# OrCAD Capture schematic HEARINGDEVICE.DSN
size A
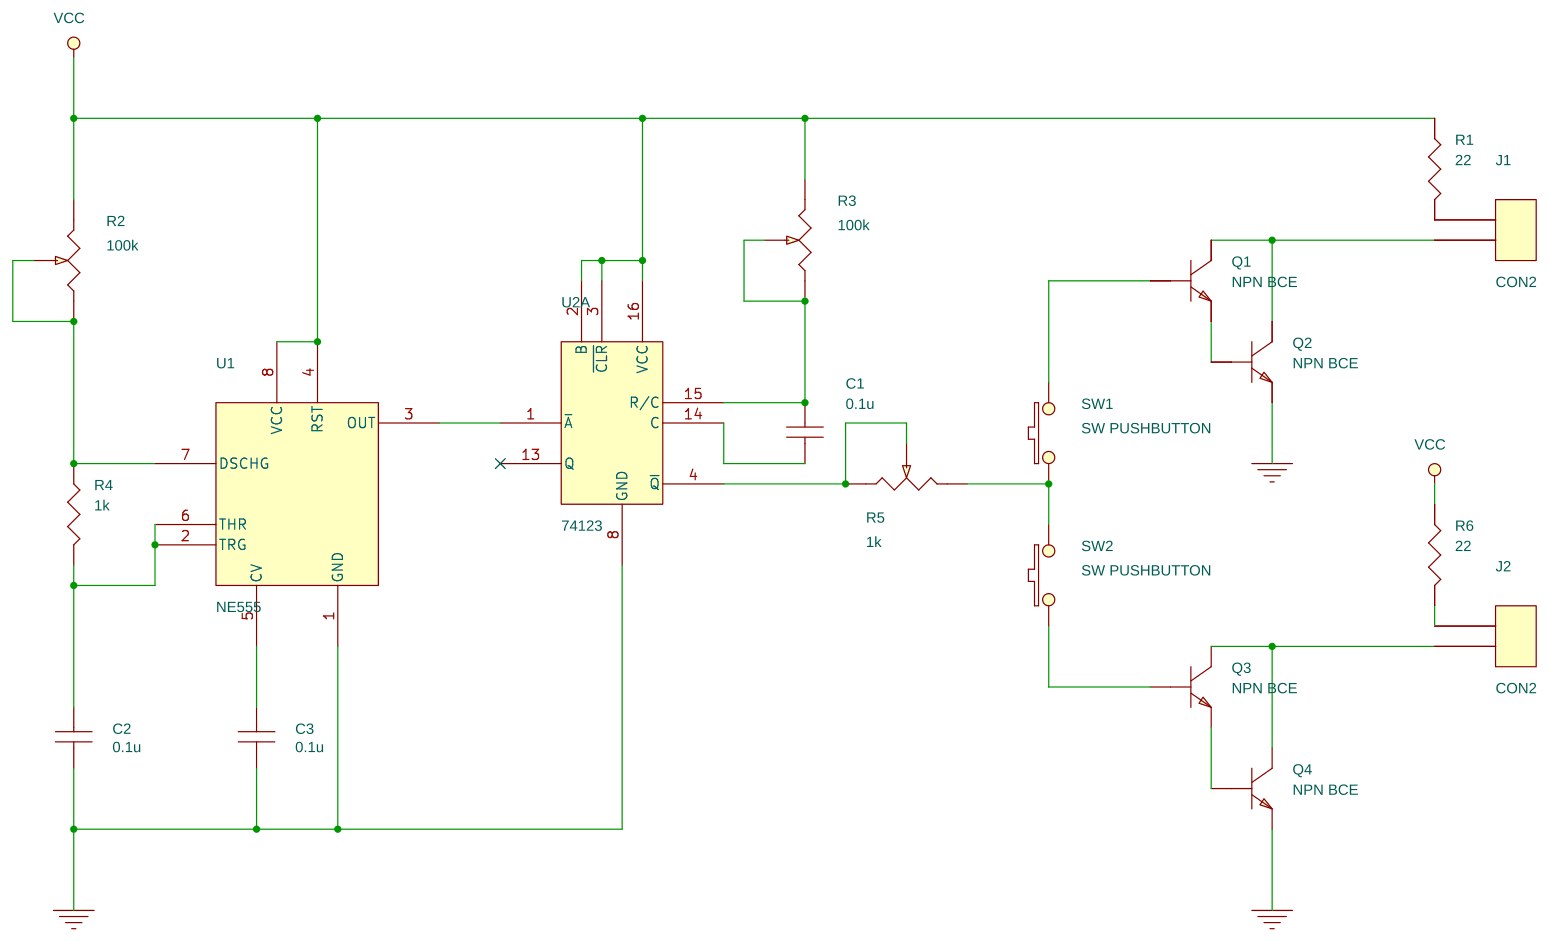
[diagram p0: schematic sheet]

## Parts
C1  0.1u  [CAPCK05]
C2  0.1u  [CAPCK05]
C3  0.1u  [CAPCK05]
J1  CON2  [JUMPER2]
J2  CON2  [JUMPER2]
Q1  NPN BCE  [TO92]
Q2  NPN BCE  [TO92]
Q3  NPN BCE  [TO92]
Q4  NPN BCE  [TO92]
R1  22  [RES400]
R2  100k  [RESADJ]
R3  100k  [RESADJ]
R4  1k  [RES400]
R5  1k  [RESADJ]
R6  22  [RES400]
SW1  SW PUSHBUTTON  [JUMPER2]
SW2  SW PUSHBUTTON  [JUMPER2]
U1  NE555  [DIP8_3]
U2  74123  [DIP16_3]  (section A)

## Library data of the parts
C1-C3 = CAP_NP
J1 J2 = CON2
Q1 Q3 Q4 = NPN_BCE
Q2 = NPN_BCE_0
R1 R4 R6 = R
R2 R3 R5 = RESISTOR_VAR
SW1 SW2 = SW_PUSHBUTTON
U1 = NE555_1
U2 = 74123_3

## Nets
GND: C2.2 C3.2 Q2.3(E) Q4.3(E) U1.1(GND) U2.8(GND)
VCC: R1.1 R2.3(B) R3.3(B) R6.1 U1.4(RST) U1.8(VCC) U2.2(B) U2.3(~{CLR}) U2.16(VCC)
N00839: R2.1(A) R2.2(WIPER) R4.1 U1.7(DSCHG)
N00856: C2.1 R4.2 U1.2(TRG) U1.6(THR)
N00875: C3.1 U1.5(CV)
N00964: U1.3(OUT) U2.1(~{A})
N01014: R5.1(A) R5.2(WIPER) U2.4(~{Q})
N01018: C1.2 U2.14(C)
N01027: C1.1 R3.1(A) R3.2(WIPER) U2.15(R/C)
N01057: R5.3(B) SW1.1 SW2.2
N01080: Q1.1(B) SW1.2
N01087: Q1.3(E) Q2.1(B)
N01091: J1.2 Q1.2(C) Q2.2(C)
N01139: Q3.1(B) SW2.1
N01146: Q3.3(E) Q4.1(B)
N01156: J2.2 Q3.2(C) Q4.2(C)
N01647: J2.1 R6.2
N04536: J1.1 R1.2

Not connected (* = marked no-connect by the designer): U2 13(Q)*
